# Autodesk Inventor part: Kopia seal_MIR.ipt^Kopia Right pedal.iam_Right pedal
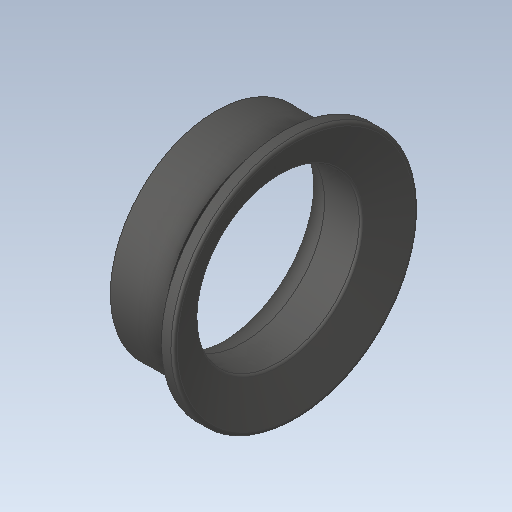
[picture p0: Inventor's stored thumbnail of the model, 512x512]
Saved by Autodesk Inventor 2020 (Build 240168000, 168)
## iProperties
Created: 2017-10
Part Number: Kopia seal_MIR.ipt^Kopia Right pedal.iam_Right pedal
Material: solidworks materials|POLIURETAN (11671)|229
Document SubType Name: Modeling
Designer: Tomasz
Density: 1.225 g/cm^3
Appearance: 0,0,0
Sending System: SolidWorks 2017
Last Author: Tomasz
Last Saved: 2017-11-19
Author: Tomasz
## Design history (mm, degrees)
feature "seal_MIR.ipt"
node "Bryła1"
